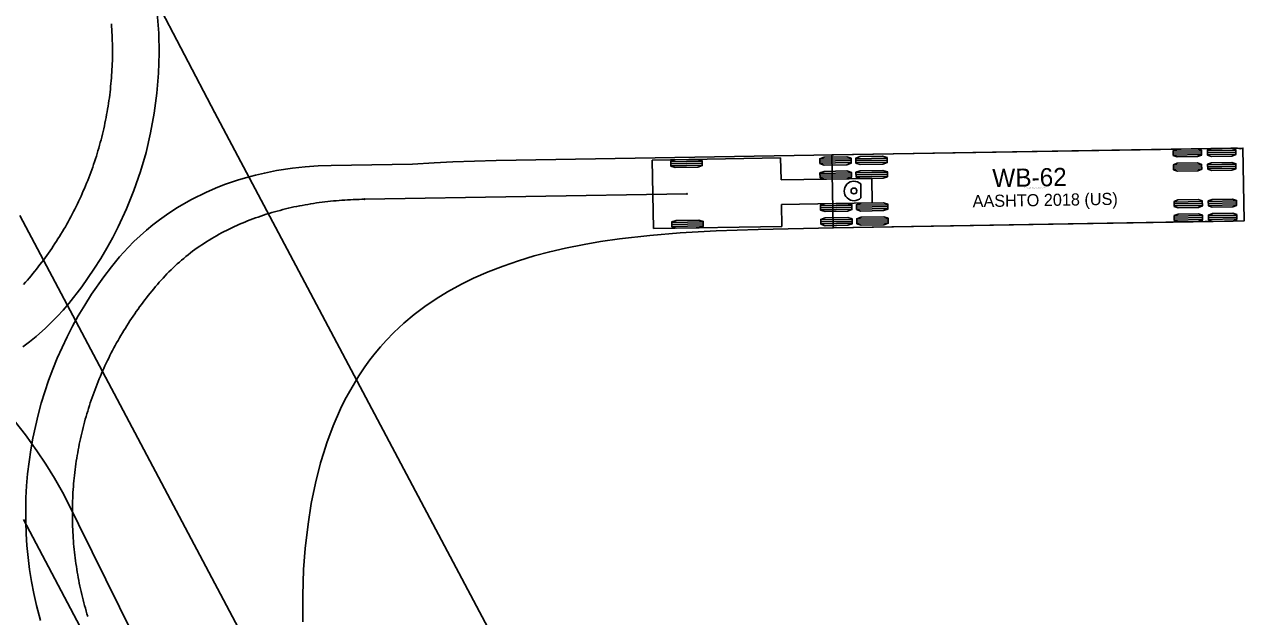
# Model space of a CAD drawing. Extents: x 2297881 to 2300600, y 559917 to 564426.
# Drawn here: x 2299397.2 to 2299541.4, y 561800.6 to 561869.7 of the extents above; entities that cross this region are included whole.
import ezdxf

# ---------------------------------------------------------------- set-up
doc = ezdxf.new("R2010")
doc.units = 0
for name, color, linetype in [('GE_X_Alignment', 7, 'Continuous'), ('PM_P_Edge_Line', 7, 'Continuous'), ('PM_P_Lane_Line', 7, 'Continuous'), ('SC_Scratch1', 7, 'Continuous'), ('SN_X_Public', 7, 'Continuous')]:
    doc.layers.add(name, color=color, linetype=linetype)

msp = doc.modelspace()

# ---------------------------------------------------------------- linework, layer by layer
at = {"layer": 'GE_X_Alignment'}
msp.add_line((2299396.64, 561847.4), (2299991.21, 560726.85), dxfattribs=at)
at = {"layer": 'PM_P_Edge_Line'}
for p, q in [((2299539.49, 561855.27), (2299491.5, 561854.47)), ((2299491.5, 561854.47), (2299491.64, 561845.97)), ((2299531.35, 561854.91), (2299534.65, 561854.96)), ((2299531.35, 561854.68), (2299534.65, 561854.73)), ((2299531.36, 561854.45), (2299534.65, 561854.5)), ((2299535.35, 561854.97), (2299538.65, 561855.03)), ((2299535.35, 561854.74), (2299538.65, 561854.8)), ((2299535.35, 561854.52), (2299538.65, 561854.57)), ((2299539.64, 561846.77), (2299539.49, 561855.27)), ((2299485.5, 561854.12), (2299470.51, 561853.87)), ((2299470.51, 561853.87), (2299470.64, 561845.87)), ((2299472.68, 561853.67), (2299476.34, 561853.73)), ((2299472.68, 561853.44), (2299476.35, 561853.5)), ((2299472.68, 561853.21), (2299476.35, 561853.28)), ((2299485.55, 561851.55), (2299485.5, 561854.12)), ((2299490.07, 561853.96), (2299493.74, 561854.03)), ((2299490.08, 561853.74), (2299493.74, 561853.8)), ((2299490.08, 561853.51), (2299493.75, 561853.57)), ((2299494.27, 561854.03), (2299497.94, 561854.1)), ((2299494.28, 561853.81), (2299497.94, 561853.87)), ((2299494.28, 561853.58), (2299497.95, 561853.64)), ((2299531.38, 561853.26), (2299534.67, 561853.31)), ((2299531.38, 561853.03), (2299534.68, 561853.08)), ((2299531.38, 561852.8), (2299534.68, 561852.85)), ((2299535.37, 561853.32), (2299538.67, 561853.38)), ((2299535.38, 561853.09), (2299538.68, 561853.15)), ((2299535.38, 561852.87), (2299538.68, 561852.92)), ((2299496.15, 561851.73), (2299485.55, 561851.55)), ((2299490.1, 561852.31), (2299493.77, 561852.38)), ((2299490.11, 561852.09), (2299493.77, 561852.15)), ((2299490.11, 561851.86), (2299493.78, 561851.92)), ((2299494.3, 561852.38), (2299497.97, 561852.45)), ((2299494.31, 561852.16), (2299497.97, 561852.22)), ((2299494.31, 561851.93), (2299497.98, 561851.99)), ((2299496.19, 561848.86), (2299496.15, 561851.73)), ((2299474.57, 561849.93), (2299436.93, 561849.3)), ((2299494.89, 561849.47), (2299494.86, 561851.08)), ((2299485.6, 561848.68), (2299496.19, 561848.86)), ((2299485.64, 561846.12), (2299485.6, 561848.68)), ((2299490.17, 561848.53), (2299493.83, 561848.59)), ((2299494.36, 561848.6), (2299498.03, 561848.66)), ((2299531.45, 561848.97), (2299534.75, 561849.03)), ((2299531.45, 561848.75), (2299534.75, 561848.8)), ((2299531.45, 561848.52), (2299534.75, 561848.57)), ((2299535.45, 561849.04), (2299538.75, 561849.1)), ((2299535.45, 561848.81), (2299538.75, 561848.87)), ((2299535.45, 561848.58), (2299538.75, 561848.64)), ((2299490.17, 561848.3), (2299493.84, 561848.36)), ((2299490.17, 561848.07), (2299493.84, 561848.13)), ((2299494.37, 561848.37), (2299498.03, 561848.43)), ((2299494.37, 561848.14), (2299498.04, 561848.21)), ((2299494.39, 561846.95), (2299498.06, 561847.01)), ((2299531.47, 561847.32), (2299534.77, 561847.38)), ((2299531.48, 561847.1), (2299534.78, 561847.15)), ((2299535.47, 561847.39), (2299538.77, 561847.45)), ((2299535.48, 561847.16), (2299538.78, 561847.22)), ((2299470.64, 561845.87), (2299485.64, 561846.12)), ((2299470.64, 561845.87), (2299470.64, 561845.87)), ((2299472.8, 561846.59), (2299476.46, 561846.65)), ((2299472.8, 561846.36), (2299476.47, 561846.42)), ((2299472.8, 561846.13), (2299476.47, 561846.19)), ((2299490.19, 561846.88), (2299493.86, 561846.94)), ((2299490.2, 561846.65), (2299493.86, 561846.71)), ((2299490.2, 561846.42), (2299493.87, 561846.49)), ((2299491.64, 561845.97), (2299539.64, 561846.77)), ((2299491.64, 561845.97), (2299491.64, 561845.97)), ((2299494.4, 561846.72), (2299498.06, 561846.78)), ((2299494.4, 561846.49), (2299498.07, 561846.56)), ((2299531.48, 561846.87), (2299534.78, 561846.92)), ((2299535.48, 561846.93), (2299538.78, 561846.99))]:
    msp.add_line(p, q, dxfattribs=at)
for points in [[(2299399.05, 561800.1), (2299398.6, 561801.85), (2299398.28, 561803.25), (2299398.02, 561804.67), (2299397.79, 561806.08), (2299397.62, 561807.47), (2299397.49, 561808.86), (2299397.4, 561810.25), (2299397.35, 561811.65), (2299397.34, 561813.05), (2299397.37, 561814.45), (2299397.45, 561815.85), (2299397.57, 561817.24), (2299397.73, 561818.64), (2299397.93, 561820.02), (2299398.18, 561821.4), (2299398.47, 561822.77), (2299398.79, 561824.13), (2299399.16, 561825.48), (2299399.57, 561826.81), (2299400.01, 561828.13), (2299400.5, 561829.44), (2299401.02, 561830.73), (2299401.58, 561832), (2299402.18, 561833.25), (2299402.82, 561834.48), (2299403.48, 561835.69), (2299404.23, 561836.94), (2299405.03, 561838.2), (2299406.46, 561840.23), (2299407.36, 561841.41), (2299408.3, 561842.56), (2299409.29, 561843.66), (2299409.98, 561844.36), (2299410.69, 561845.04), (2299411.43, 561845.69), (2299412.19, 561846.31), (2299412.97, 561846.91), (2299413.77, 561847.48), (2299415, 561848.28), (2299416.69, 561849.25), (2299418.45, 561850.12), (2299419.79, 561850.69), (2299420.69, 561851.04), (2299422.07, 561851.51), (2299423, 561851.79), (2299424.16, 561852.1), (2299425.22, 561852.35), (2299426.65, 561852.64), (2299428.48, 561852.91), (2299429.98, 561853.08), (2299431.5, 561853.18), (2299433.03, 561853.24), (2299442.53, 561853.4), (2299445.06, 561853.56), (2299447.23, 561853.67), (2299452.28, 561853.81), (2299538.07, 561855.25), (2299538.85, 561855.24), (2299539.18, 561855.19), (2299539.49, 561855.27), (2299539.64, 561846.77), (2299538.34, 561846.75)], [(2299436.93, 561849.3), (2299436.6, 561849.29), (2299436.27, 561849.28), (2299435.93, 561849.27), (2299435.6, 561849.26), (2299435.27, 561849.24), (2299434.93, 561849.22), (2299434.6, 561849.2), (2299434.27, 561849.18), (2299433.94, 561849.15), (2299433.6, 561849.12), (2299433.27, 561849.09), (2299432.94, 561849.06), (2299432.61, 561849.02), (2299432.28, 561848.99), (2299431.95, 561848.95), (2299431.62, 561848.9), (2299431.29, 561848.86), (2299430.96, 561848.81), (2299430.63, 561848.76), (2299430.3, 561848.7), (2299429.97, 561848.64), (2299429.64, 561848.58), (2299429.32, 561848.52), (2299428.99, 561848.46), (2299428.66, 561848.39), (2299428.34, 561848.32), (2299428.01, 561848.24), (2299427.69, 561848.17), (2299427.36, 561848.09), (2299427.04, 561848), (2299426.72, 561847.92), (2299426.4, 561847.83), (2299426.08, 561847.73), (2299425.76, 561847.64), (2299425.44, 561847.54), (2299425.12, 561847.44), (2299424.81, 561847.33), (2299424.49, 561847.22), (2299424.18, 561847.11), (2299423.86, 561847), (2299423.55, 561846.88), (2299423.24, 561846.76), (2299422.93, 561846.63), (2299422.63, 561846.5), (2299422.32, 561846.37), (2299422.01, 561846.24), (2299421.71, 561846.1), (2299421.41, 561845.96), (2299421.11, 561845.81), (2299420.81, 561845.66), (2299420.52, 561845.51), (2299420.22, 561845.36), (2299419.93, 561845.2), (2299419.64, 561845.03), (2299419.35, 561844.87), (2299419.06, 561844.7), (2299418.78, 561844.53), (2299418.49, 561844.35), (2299418.21, 561844.17), (2299417.93, 561843.99), (2299417.66, 561843.8), (2299417.38, 561843.61), (2299417.11, 561843.41), (2299416.84, 561843.22), (2299416.58, 561843.02), (2299416.31, 561842.81), (2299416.05, 561842.6), (2299415.8, 561842.39), (2299415.54, 561842.18), (2299415.29, 561841.96), (2299415.04, 561841.74), (2299414.79, 561841.51), (2299414.55, 561841.29), (2299414.31, 561841.05), (2299414.07, 561840.82), (2299413.84, 561840.58), (2299413.61, 561840.34), (2299413.38, 561840.1), (2299413.16, 561839.85), (2299412.94, 561839.6), (2299412.72, 561839.35), (2299412.51, 561839.09), (2299412.29, 561838.84), (2299412.08, 561838.58), (2299411.87, 561838.32), (2299411.66, 561838.06), (2299411.45, 561837.8), (2299411.25, 561837.54), (2299411.05, 561837.27), (2299410.85, 561837), (2299410.65, 561836.73), (2299410.46, 561836.46), (2299410.26, 561836.19), (2299410.07, 561835.92), (2299409.88, 561835.64), (2299409.7, 561835.37), (2299409.51, 561835.09), (2299409.33, 561834.81), (2299409.15, 561834.53), (2299408.98, 561834.25), (2299408.8, 561833.96), (2299408.63, 561833.68), (2299408.46, 561833.39), (2299408.29, 561833.1), (2299408.12, 561832.82), (2299407.96, 561832.52), (2299407.8, 561832.23), (2299407.64, 561831.94), (2299407.49, 561831.64), (2299407.33, 561831.35), (2299407.18, 561831.05), (2299407.03, 561830.75), (2299406.89, 561830.45), (2299406.74, 561830.15), (2299406.6, 561829.85), (2299406.46, 561829.55), (2299406.32, 561829.24), (2299406.19, 561828.94), (2299406.06, 561828.63), (2299405.93, 561828.33), (2299405.8, 561828.02), (2299405.68, 561827.71), (2299405.56, 561827.4), (2299405.44, 561827.09), (2299405.32, 561826.77), (2299405.21, 561826.46), (2299405.1, 561826.15), (2299404.99, 561825.83), (2299404.88, 561825.52), (2299404.78, 561825.2), (2299404.68, 561824.88), (2299404.58, 561824.56), (2299404.48, 561824.24), (2299404.39, 561823.92), (2299404.3, 561823.6), (2299404.21, 561823.28), (2299404.12, 561822.96), (2299404.04, 561822.64), (2299403.96, 561822.31), (2299403.88, 561821.99), (2299403.81, 561821.66), (2299403.73, 561821.34), (2299403.66, 561821.01), (2299403.6, 561820.69), (2299403.53, 561820.36), (2299403.47, 561820.03), (2299403.41, 561819.7), (2299403.35, 561819.38), (2299403.3, 561819.05), (2299403.25, 561818.72), (2299403.2, 561818.39), (2299403.16, 561818.06), (2299403.11, 561817.73), (2299403.07, 561817.4), (2299403.03, 561817.06), (2299403, 561816.73), (2299402.97, 561816.4), (2299402.94, 561816.07), (2299402.91, 561815.74), (2299402.89, 561815.4), (2299402.86, 561815.07), (2299402.85, 561814.74), (2299402.83, 561814.41), (2299402.82, 561814.07), (2299402.81, 561813.74), (2299402.8, 561813.41), (2299402.79, 561813.07), (2299402.79, 561812.74), (2299402.79, 561812.41), (2299402.79, 561812.07), (2299402.8, 561811.74), (2299402.81, 561811.41), (2299402.82, 561811.07), (2299402.83, 561810.74), (2299402.85, 561810.41), (2299402.87, 561810.08), (2299402.89, 561809.74), (2299402.91, 561809.41), (2299402.94, 561809.08), (2299402.97, 561808.75), (2299403, 561808.41), (2299403.04, 561808.08), (2299403.08, 561807.75), (2299403.12, 561807.42), (2299403.16, 561807.09), (2299403.21, 561806.76), (2299403.26, 561806.43), (2299403.31, 561806.1), (2299403.36, 561805.77), (2299403.42, 561805.44), (2299403.48, 561805.12), (2299403.54, 561804.79), (2299403.6, 561804.46), (2299403.67, 561804.13), (2299403.74, 561803.81), (2299403.81, 561803.48), (2299403.89, 561803.16), (2299403.97, 561802.84), (2299404.05, 561802.51), (2299404.13, 561802.19), (2299404.22, 561801.87), (2299404.31, 561801.55), (2299404.4, 561801.22), (2299404.49, 561800.9), (2299404.59, 561800.59)], [(2299538.34, 561846.75), (2299491.7, 561845.97), (2299482.88, 561845.77), (2299477.99, 561845.59), (2299473.77, 561845.36), (2299470.22, 561845.07), (2299466.69, 561844.67), (2299464.47, 561844.35), (2299462.58, 561844.03), (2299460.39, 561843.59), (2299458.54, 561843.16), (2299456.71, 561842.67), (2299454.9, 561842.12), (2299453.12, 561841.5), (2299451.37, 561840.82), (2299449.65, 561840.07), (2299448.25, 561839.38), (2299446.6, 561838.48), (2299445.27, 561837.67), (2299443.97, 561836.79), (2299442.71, 561835.84), (2299441.49, 561834.83), (2299440.32, 561833.74), (2299439.42, 561832.81), (2299438.77, 561832.08), (2299438.14, 561831.33), (2299437.53, 561830.55), (2299436.94, 561829.74), (2299436.23, 561828.66), (2299435.18, 561826.9), (2299434.62, 561825.86), (2299434.12, 561824.84), (2299433.25, 561822.83), (2299432.51, 561820.86), (2299432.14, 561819.71), (2299431.78, 561818.53), (2299431.18, 561816.15), (2299430.69, 561813.77), (2299430.31, 561811.37), (2299429.98, 561808.53), (2299429.8, 561806.08), (2299429.7, 561803.02), (2299429.72, 561799.96)]]:
    msp.add_lwpolyline(points, dxfattribs=at)
for points in [[(2299490.08, 561853.45), (2299490.07, 561854.02), (2299490.58, 561854.2), (2299493.22, 561854.25), (2299493.74, 561854.08), (2299493.75, 561853.51), (2299493.24, 561853.33), (2299490.6, 561853.29)], [(2299494.28, 561853.52), (2299494.27, 561854.09), (2299494.78, 561854.27), (2299497.42, 561854.32), (2299497.94, 561854.15), (2299497.95, 561853.58), (2299497.44, 561853.4), (2299494.8, 561853.36)], [(2299531.36, 561854.39), (2299531.35, 561854.96), (2299531.81, 561855.14), (2299534.18, 561855.18), (2299534.65, 561855.02), (2299534.66, 561854.45), (2299534.2, 561854.27), (2299531.82, 561854.23)], [(2299535.36, 561854.46), (2299535.35, 561855.03), (2299535.81, 561855.21), (2299538.18, 561855.25), (2299538.65, 561855.09), (2299538.66, 561854.51), (2299538.2, 561854.33), (2299535.82, 561854.29)], [(2299472.69, 561853.16), (2299472.68, 561853.73), (2299473.19, 561853.91), (2299475.83, 561853.95), (2299476.34, 561853.79), (2299476.35, 561853.22), (2299475.84, 561853.04), (2299473.2, 561852.99)], [(2299531.38, 561852.74), (2299531.37, 561853.31), (2299531.83, 561853.49), (2299534.21, 561853.53), (2299534.67, 561853.37), (2299534.68, 561852.8), (2299534.22, 561852.62), (2299531.85, 561852.58)], [(2299535.38, 561852.81), (2299535.37, 561853.38), (2299535.83, 561853.56), (2299538.21, 561853.6), (2299538.67, 561853.44), (2299538.68, 561852.86), (2299538.22, 561852.68), (2299535.85, 561852.64)], [(2299490.11, 561851.8), (2299490.1, 561852.37), (2299490.61, 561852.55), (2299493.25, 561852.6), (2299493.77, 561852.43), (2299493.78, 561851.86), (2299493.27, 561851.68), (2299490.63, 561851.64)], [(2299494.31, 561851.87), (2299494.3, 561852.44), (2299494.81, 561852.62), (2299497.45, 561852.67), (2299497.97, 561852.5), (2299497.98, 561851.93), (2299497.47, 561851.75), (2299494.83, 561851.71)], [(2299490.17, 561848.02), (2299490.16, 561848.59), (2299490.67, 561848.77), (2299493.31, 561848.81), (2299493.83, 561848.65), (2299493.84, 561848.08), (2299493.33, 561847.9), (2299490.69, 561847.85)], [(2299494.37, 561848.09), (2299494.36, 561848.66), (2299494.87, 561848.84), (2299497.51, 561848.88), (2299498.03, 561848.72), (2299498.04, 561848.15), (2299497.53, 561847.97), (2299494.89, 561847.92)], [(2299531.46, 561848.46), (2299531.45, 561849.03), (2299531.91, 561849.21), (2299534.28, 561849.25), (2299534.75, 561849.09), (2299534.76, 561848.51), (2299534.3, 561848.33), (2299531.92, 561848.29)], [(2299535.46, 561848.53), (2299535.45, 561849.1), (2299535.9, 561849.28), (2299538.28, 561849.32), (2299538.75, 561849.15), (2299538.75, 561848.58), (2299538.3, 561848.4), (2299535.92, 561848.36)], [(2299490.2, 561846.37), (2299490.19, 561846.94), (2299490.7, 561847.12), (2299493.34, 561847.16), (2299493.86, 561847), (2299493.87, 561846.43), (2299493.36, 561846.25), (2299490.72, 561846.2)], [(2299494.4, 561846.44), (2299494.39, 561847.01), (2299494.9, 561847.19), (2299497.54, 561847.23), (2299498.06, 561847.07), (2299498.07, 561846.5), (2299497.56, 561846.32), (2299494.92, 561846.27)], [(2299531.48, 561846.81), (2299531.47, 561847.38), (2299531.93, 561847.56), (2299534.31, 561847.6), (2299534.77, 561847.44), (2299534.78, 561846.86), (2299534.32, 561846.68), (2299531.95, 561846.64)], [(2299535.48, 561846.88), (2299535.47, 561847.45), (2299535.93, 561847.63), (2299538.31, 561847.67), (2299538.77, 561847.5), (2299538.78, 561846.93), (2299538.32, 561846.75), (2299535.95, 561846.71)], [(2299472.8, 561846.07), (2299472.79, 561846.65), (2299473.31, 561846.83), (2299475.94, 561846.87), (2299476.46, 561846.71), (2299476.47, 561846.14), (2299475.96, 561845.96), (2299473.32, 561845.91)]]:
    msp.add_lwpolyline(points, close=True, dxfattribs=at)
for centre, radius in [((2299474.57, 561849.93), 0.0417), ((2299494.07, 561850.26), 0.34), ((2299436.93, 561849.3), 0.0417)]:
    msp.add_circle(centre, radius, dxfattribs=at)
msp.add_arc((2299494.07, 561850.26), 1.14, 45.9612, 315.9612, dxfattribs=at)
at = {"layer": 'PM_P_Lane_Line'}
for p, q in [((2298843.32, 562963.26), (2299419.43, 561859.39)), ((2299419.39, 561859.47), (2299927.35, 560902.13))]:
    msp.add_line(p, q, dxfattribs=at)
at = {"layer": 'SC_Scratch1'}
for points in [[(2299412.71, 561871.03), (2299412.88, 561868.69), (2299412.92, 561866.35), (2299412.85, 561864.01), (2299412.66, 561861.67), (2299412.35, 561859.35), (2299411.93, 561857.04), (2299411.39, 561854.77), (2299410.74, 561852.52), (2299409.98, 561850.32), (2299409.11, 561848.16), (2299408.13, 561846.06), (2299407.5, 561844.82), (2299406.83, 561843.6), (2299406.11, 561842.38), (2299405.3, 561841.12), (2299403.88, 561839.07), (2299402.36, 561837.12), (2299401.73, 561836.36), (2299401.06, 561835.63), (2299400.37, 561834.93), (2299399.66, 561834.25), (2299398.55, 561833.28), (2299397.78, 561832.66), (2299396.99, 561832.08)], [(2299397.1, 561839.35), (2299397.32, 561839.6), (2299397.54, 561839.85), (2299397.76, 561840.1), (2299397.97, 561840.36), (2299398.18, 561840.62), (2299398.39, 561840.88), (2299398.6, 561841.14), (2299398.81, 561841.4), (2299399.01, 561841.66), (2299399.21, 561841.93), (2299399.41, 561842.19), (2299399.61, 561842.46), (2299399.8, 561842.73), (2299400, 561843), (2299400.19, 561843.28), (2299400.38, 561843.55), (2299400.56, 561843.83), (2299400.75, 561844.11), (2299400.93, 561844.39), (2299401.11, 561844.67), (2299401.29, 561844.95), (2299401.46, 561845.23), (2299401.63, 561845.52), (2299401.8, 561845.81), (2299401.97, 561846.09), (2299402.14, 561846.38), (2299402.3, 561846.67), (2299402.46, 561846.97), (2299402.62, 561847.26), (2299402.78, 561847.55), (2299402.93, 561847.85), (2299403.08, 561848.15), (2299403.23, 561848.44), (2299403.38, 561848.74), (2299403.52, 561849.04), (2299403.66, 561849.35), (2299403.8, 561849.65), (2299403.94, 561849.95), (2299404.07, 561850.26), (2299404.2, 561850.56), (2299404.33, 561850.87), (2299404.46, 561851.18), (2299404.58, 561851.49), (2299404.7, 561851.8), (2299404.82, 561852.11), (2299404.94, 561852.42), (2299405.05, 561852.74), (2299405.17, 561853.05), (2299405.27, 561853.37), (2299405.38, 561853.68), (2299405.48, 561854), (2299405.59, 561854.32), (2299405.68, 561854.63), (2299405.78, 561854.95), (2299405.87, 561855.27), (2299405.96, 561855.59), (2299406.05, 561855.92), (2299406.14, 561856.24), (2299406.22, 561856.56), (2299406.3, 561856.88), (2299406.38, 561857.21), (2299406.45, 561857.53), (2299406.53, 561857.86), (2299406.6, 561858.18), (2299406.66, 561858.51), (2299406.73, 561858.84), (2299406.79, 561859.17), (2299406.85, 561859.49), (2299406.91, 561859.82), (2299406.96, 561860.15), (2299407.01, 561860.48), (2299407.06, 561860.81), (2299407.11, 561861.14), (2299407.15, 561861.47), (2299407.19, 561861.8), (2299407.23, 561862.13), (2299407.26, 561862.46), (2299407.29, 561862.8), (2299407.32, 561863.13), (2299407.35, 561863.46), (2299407.37, 561863.79), (2299407.4, 561864.13), (2299407.41, 561864.46), (2299407.43, 561864.79), (2299407.44, 561865.12), (2299407.46, 561865.46), (2299407.46, 561865.79), (2299407.47, 561866.12), (2299407.47, 561866.46), (2299407.47, 561866.79), (2299407.47, 561867.12), (2299407.46, 561867.46), (2299407.45, 561867.79), (2299407.44, 561868.12), (2299407.43, 561868.46), (2299407.41, 561868.79), (2299407.39, 561869.12), (2299407.37, 561869.45), (2299407.35, 561869.79)]]:
    msp.add_lwpolyline(points, dxfattribs=at)
at = {"layer": 'SN_X_Public'}
msp.add_line((2299397.07, 561811.91), (2299461.04, 561691.4), dxfattribs=at)
msp.add_lwpolyline([(2299396.16, 561823.27), (2299397.32, 561821.78), (2299398.65, 561819.94), (2299399.7, 561818.36), (2299400.7, 561816.74), (2299401.63, 561815.09), (2299402.34, 561813.74), (2299403.52, 561811.37), (2299411.5, 561795.2)], dxfattribs=at)

# ---------------------------------------------------------------- texts
at = {"layer": 'PM_P_Edge_Line'}
for s, height, p in [('WB-62', 2.125, (2299510.25, 561850.7)), ('AASHTO 2018 (US)', 1.4167, (2299507.94, 561848.36)), ('(c) 2021 Transoft Solutions, Inc. All rights reserved.', 0.085, (2299513.84, 561850.55))]:
    msp.add_text(s, height=height, rotation=0.9612, dxfattribs=at).set_placement(p)

doc.saveas('drawing.dxf')
